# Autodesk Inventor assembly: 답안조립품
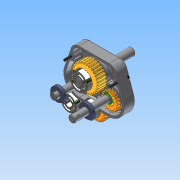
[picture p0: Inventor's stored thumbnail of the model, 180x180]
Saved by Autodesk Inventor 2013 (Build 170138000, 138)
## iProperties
Created: 2014-12
Part Number: 답안조립품
Document SubType Name: Assembly
Designer: Administrator
Author: Administrator
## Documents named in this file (14)
- C:\Users\Administrator\Desktop\441209V1043\답안조립품.iam
- C:\Users\Administrator\Desktop\441209V1043\본체.ipt
- C:\Users\Administrator\Desktop\441209V1043\M 5 x 35.ipt
- C:\Users\Administrator\Desktop\441209V1043\멈춤링.ipt
- C:\Users\Administrator\Desktop\441209V1043\메인기어.ipt
- C:\Users\Administrator\Desktop\441209V1043\메인축.ipt
- C:\Users\Administrator\Desktop\441209V1043\베어링- 6202.ipt
- C:\Users\Administrator\Desktop\441209V1043\베어링- 6203.ipt
- C:\Users\Administrator\Desktop\441209V1043\서브기어.ipt
- C:\Users\Administrator\Desktop\441209V1043\서브축.ipt
- C:\Users\Administrator\Desktop\441209V1043\오일시일-D-15.ipt
- C:\Users\Administrator\Desktop\441209V1043\오일시일-D-17.ipt
- C:\Users\Administrator\Desktop\441209V1043\커버.ipt
- C:\Users\Administrator\Desktop\441209V1043\키5x5.ipt
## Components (15 placed, 6 different names)
1. KS B 1003 - 미터 M 5 x 35:1
2. KS B 1336 17 x 1:1
3. KS B 2023 6202 - 15 x 35 x 11:1
4. KS B 2023 6203 - 17 x 40 x 12:1
5. KS B 2804 D D - 15 30 7:1
6. KS B 2804 D D - 17 30 8:1
7. KS B 2804 D D - 15 30 7:2
8. KS B 1336 17 x 1:2
9. KS B 1336 17 x 1:3
10. KS B 2023 6203 - 17 x 40 x 12:2
11. KS B 2023 6202 - 15 x 35 x 11:2
12. KS B 2023 6202 - 15 x 35 x 11:3
13. KS B 2023 6202 - 15 x 35 x 11:4
14. KS B 1003 - 미터 M 5 x 35:2
15. KS B 1003 - 미터 M 5 x 35:3
